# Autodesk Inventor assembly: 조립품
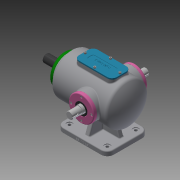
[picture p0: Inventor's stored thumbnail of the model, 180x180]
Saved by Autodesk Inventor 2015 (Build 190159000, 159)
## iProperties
Created: 2021-11
Part Number: 조립품
Document SubType Name: Assembly
Designer: 101698
Author: 101698
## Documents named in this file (13)
- C:\Users\101698\Desktop\711106V1012\답안조립품.iam
- C:\Users\101698\Desktop\711106V1012\베어링 6205.ipt
- 베어링 6205.ipt
- C:\Users\101698\Desktop\711106V1012\본체.ipt
- C:\Users\101698\Desktop\711106V1012\볼트 M4x0.7.ipt
- C:\Users\101698\Desktop\711106V1012\부시.ipt
- C:\Users\101698\Desktop\711106V1012\상부커버.ipt
- C:\Users\101698\Desktop\711106V1012\슬라이드 커버.ipt
- C:\Users\101698\Desktop\711106V1012\슬라이드.ipt
- C:\Users\101698\Desktop\711106V1012\오일실.ipt
- 오일실.ipt
- C:\Users\101698\Desktop\711106V1012\축 커버.ipt
- C:\Users\101698\Desktop\711106V1012\편심축.ipt
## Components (12 placed, 1 different names)
1. M4x0.7:1
2. M4x0.7:2
3. M4x0.7:5
4. M4x0.7:6
5. M4x0.7:3
6. M4x0.7:7
7. M4x0.7:8
8. M4x0.7:9
9. M4x0.7:4
10. M4x0.7:10
11. M4x0.7:11
12. M4x0.7:12
